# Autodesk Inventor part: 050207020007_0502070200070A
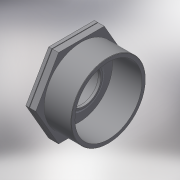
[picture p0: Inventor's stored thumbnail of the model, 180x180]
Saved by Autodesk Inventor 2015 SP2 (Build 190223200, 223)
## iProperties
Created: 2017-05
Part Number: 050207020007_0502070200070A
Material: Generic
Description: PLASSON REDUCING BUSHING 2"-3/4"
Document SubType Name: Modeling
Designer: KIM
Density: 1 g/cm^3
Appearance: Default
Author: KIM
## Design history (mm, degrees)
derived "050207.ipt"
feature "Solid1::050207.ipt"
tag "TaggingFeature1"
body "Solid1"
other parameters: "d1" = 59.614, "d2" = 63, "d5" = 25, "d8" = 0.41, "d12" = 0, "d15" = 41, "d19" = 0, "d30" = 10.25, "d31" = 5.125, "d33" = 24.117, "d34" = 53.6526, "d36" = 3.15, "d37" = 28.9404, "d38" = 27.06, "d39" = 21.7053, "d40" = 2.5, "d41" = 0, "H_" = 41, "R_" = 59.614, "E_" = 63, "l_2" = 25, "Rp_" = 24.117
